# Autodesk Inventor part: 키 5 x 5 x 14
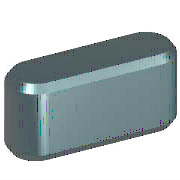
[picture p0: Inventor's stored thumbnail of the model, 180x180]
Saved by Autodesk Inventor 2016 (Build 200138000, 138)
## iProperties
IsCustomPart: 1
Created: 2012-02
Part Number: 키 5 x 5 x 14
Material: 강철, 연강
Description: 키 및 해당 키홈
Document SubType Name: Modeling
Standard: KS B 1311
Designer: mduedu
Standards Organization: KS
Language: ko-KR
Size Designation: 4 x 4 x 12
Categories: <MemberInstance><Categories><Category DisplayName="샤프트 부품" InternalName="7f7aeb1f-a693-4053-b835-cee3144e0d98" Mnemonic="SHFT"><Category DisplayName="키" Interna
Density: 1 g/cm^3
Appearance: 노란색
Author: mduedu
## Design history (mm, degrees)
workplane "Work Plane1"
workplane "Work Plane2"
sketch "스케치1"
  geometry: L1 (2.5, 2.5)-(11.5, 2.5); L2 (11.5, -2.5)-(2.5, -2.5); L3 (0, 8.9)-(0, -4.4) reference; L4 (-2.8, 0)-(16.8, 0) reference; L5 (14, 0)-(14, 7); A1 r 2.5 centre (2.5, 0) between (2.5, 2.5) and (2.5, -2.5); A2 r 2.5 centre (11.5, 0) between (11.5, -2.5) and (11.5, 2.5)
  constraints: 6 end point, 5 point on circle, 4 tangent, 3 point on line, 2 centre point, 1 horizontal, 1 parallel, 1 perpendicular
  dimensions: "d0" = 2.5 radius of A1 (= 0.5 x PB); "d13" = 2.5 radius of A2 (= 0.5 x PB); "d14" = 14 distance between parallel lines of L5 L3 (= NLG)
extrude "본체1" new body sketch "스케치1" taper "d3" = 0 deg; stored distance "d4" = 10
workplane "Work Plane3"
body "Solid1"
chamfer "모따기1" distance "d8" = 0.25 (= PHH); stored, may be unused: second distance "d9" = 0.25 (= PHH), angle "d15" = 45 deg
other parameters: "d1" = -3 (= -PNT), "d2" = 2 (= PH - PNT), "NLG" = 14 [user parameter; used in 3 equation terms], "PB" = 5 [user parameter; used in 2 equation terms], "PNT" = 3 [user parameter; used in 2 equation terms], "PH" = 5 [user parameter; used in 1 equation term], "PHH" = 0.25 [user parameter; used in 2 equation terms], "d10" = 0, "d16" = 0, "d17" = 0, "d18" = 0, "PLB2" = 14 (= NLG) [user parameter], "WDMAX" = 12 [user parameter], "PLB1" = 14 (= NLG) [user parameter], "RR" = 0.08 [user parameter], "PUEB" = 1.8 [user parameter]
